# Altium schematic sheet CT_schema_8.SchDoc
size 296 x 239 mm
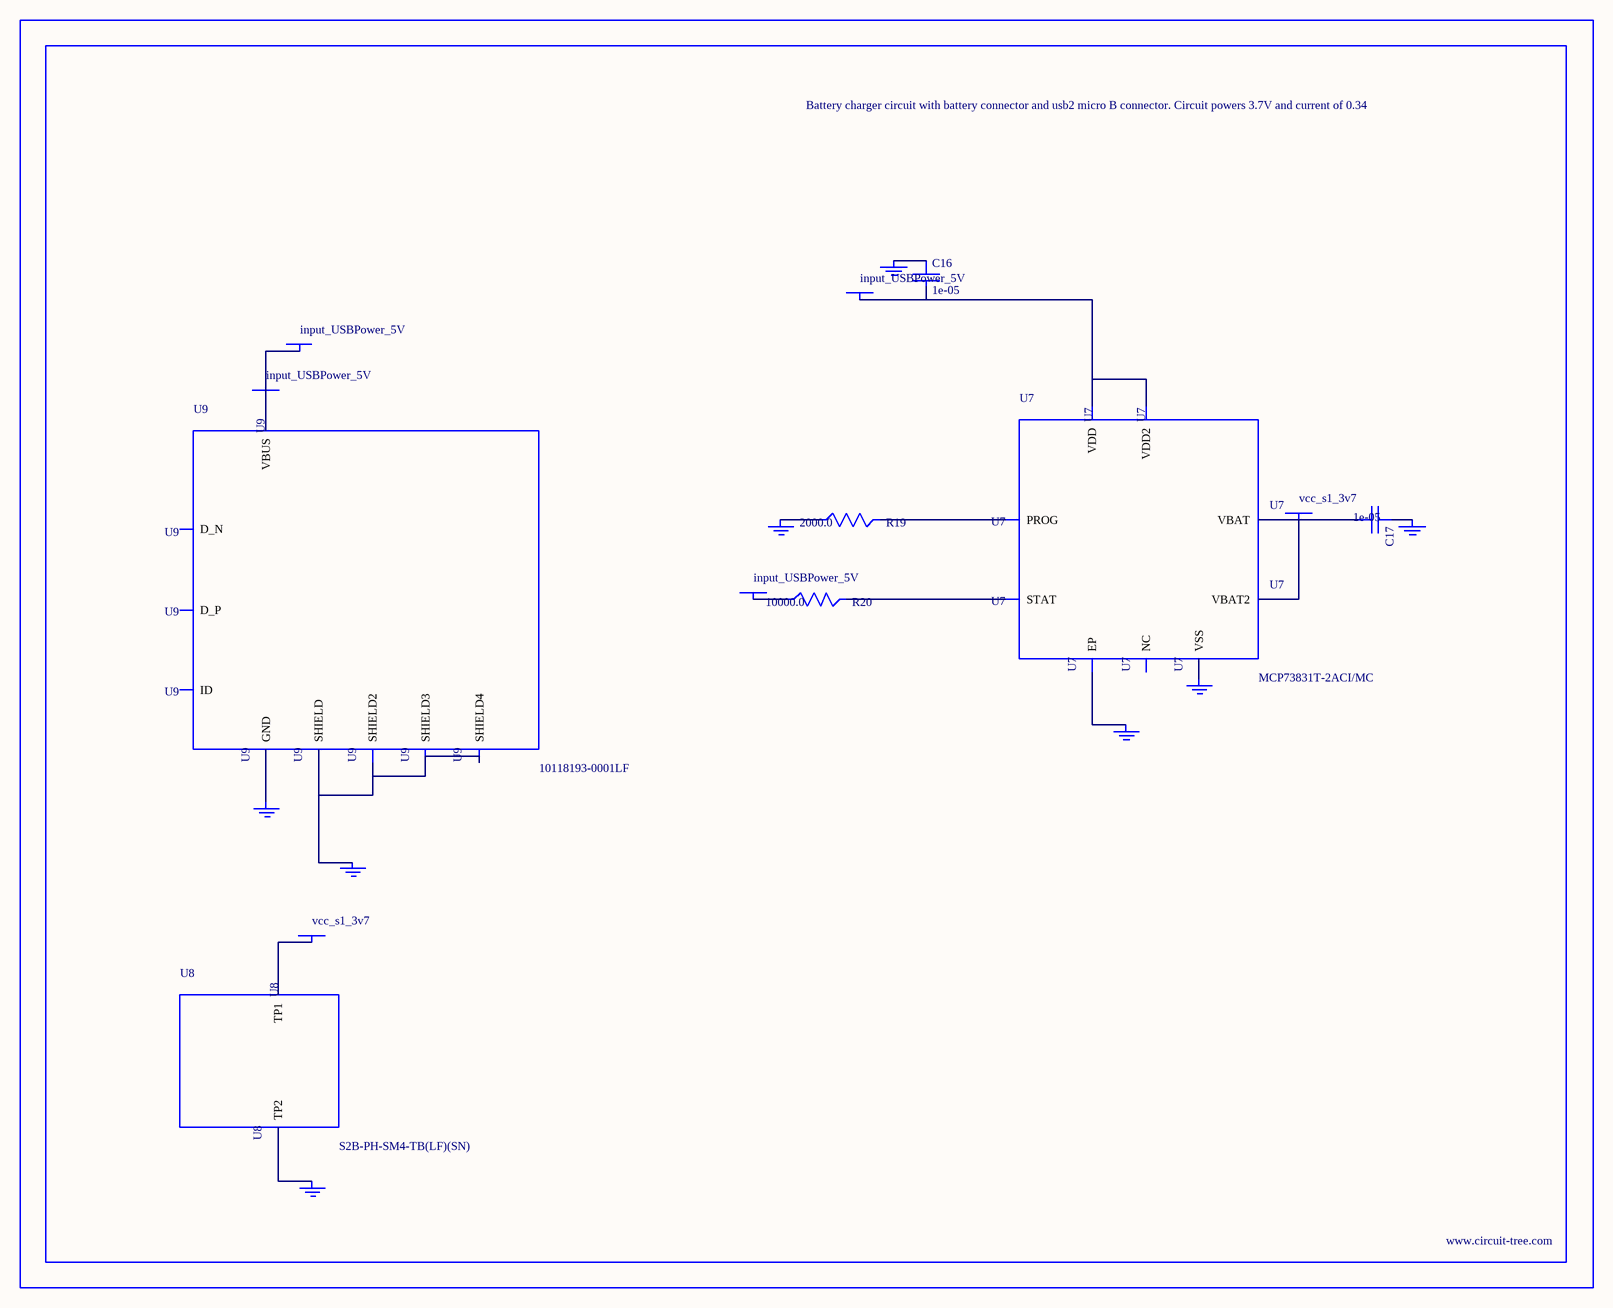
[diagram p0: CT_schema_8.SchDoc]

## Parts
BORDER7  (no value)
C16  1e-05  [C1206]
C17  1e-05  [C1206]
GND_INSTANCE_7_0  (no value)
GND_INSTANCE_7_1  (no value)
GND_INSTANCE_7_2  (no value)
GND_INSTANCE_7_3  (no value)
GND_INSTANCE_7_4  (no value)
GND_INSTANCE_7_5  (no value)
GND_INSTANCE_7_6  (no value)
GND_INSTANCE_7_7  (no value)
POWER_INSTANCE_7_0  input_USBPower_5V
POWER_INSTANCE_7_1  input_USBPower_5V
POWER_INSTANCE_7_2  vcc_s1_3v7
POWER_INSTANCE_7_3  vcc_s1_3v7
POWER_INSTANCE_7_4  input_USBPower_5V
POWER_INSTANCE_7_5  input_USBPower_5V
R19  2000.0  [R0603]
R20  10000.0  [R0603]
U7  MCP73831T-2ACI/MC  [DFN8_2X3MC]
U8  S2B-PH-SM4-TB(LF)(SN)  [JST-2-SMD]
U9  10118193-0001LF  [FCI_10118193-0001LF]

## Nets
NetC16_1: C16.1 GND_INSTANCE_7_0.0(GND)
NetC16_2: C16.2 POWER_INSTANCE_7_0.0(PWR) U7.1(VDD) U7.2(VDD2)
NetC17_1: C17.1 GND_INSTANCE_7_1.0(GND)
NetC17_2: C17.2 POWER_INSTANCE_7_2.0(PWR) U7.3(VBAT) U7.4(VBAT2)
NetGND_INSTANCE_7_2_0: GND_INSTANCE_7_2.0(GND) R19.1
NetGND_INSTANCE_7_3_0: GND_INSTANCE_7_3.0(GND) U7.9(EP)
NetGND_INSTANCE_7_4_0: GND_INSTANCE_7_4.0(GND) U7.6(VSS)
NetGND_INSTANCE_7_5_0: GND_INSTANCE_7_5.0(GND) U8.2(TP2)
NetGND_INSTANCE_7_6_0: GND_INSTANCE_7_6.0(GND) U9.6(SHIELD) U9.7(SHIELD2) U9.8(SHIELD3) U9.9(SHIELD4)
NetGND_INSTANCE_7_7_0: GND_INSTANCE_7_7.0(GND) U9.5(GND)
NetPOWER_INSTANCE_7_1_0: POWER_INSTANCE_7_1.0(PWR) R20.1
NetPOWER_INSTANCE_7_3_0: POWER_INSTANCE_7_3.0(PWR) U8.1(TP1)
NetPOWER_INSTANCE_7_4_0: POWER_INSTANCE_7_4.0(PWR) POWER_INSTANCE_7_5.0(PWR) U9.1(VBUS)
NetR19_2: R19.2 U7.8(PROG)
NetR20_2: R20.2 U7.5(STAT)

Not connected (* = marked no-connect by the designer): U7 7(NC); U9 2(D_N) 3(D_P) 4(ID)

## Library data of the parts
BORDER7 = BORDER_PAGE7
C16 C17 = C1206C106K3RACTU
GND_INSTANCE_7_0-GND_INSTANCE_7_7 = GND
POWER_INSTANCE_7_0-POWER_INSTANCE_7_5 = PWR
R19 = RC0603JR-072KL
R20 = RC0603JR-0710KL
